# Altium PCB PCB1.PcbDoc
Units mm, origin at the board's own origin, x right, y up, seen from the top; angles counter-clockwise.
Board outline 37.46 x 26.8 mm, 4 copper layers (L1 (Signal), L2 (GND), L3 (GND), L4 (Signal)), stack 1.57 mm thick; 35 components, 27 nets, 170 pads, 47 vias.
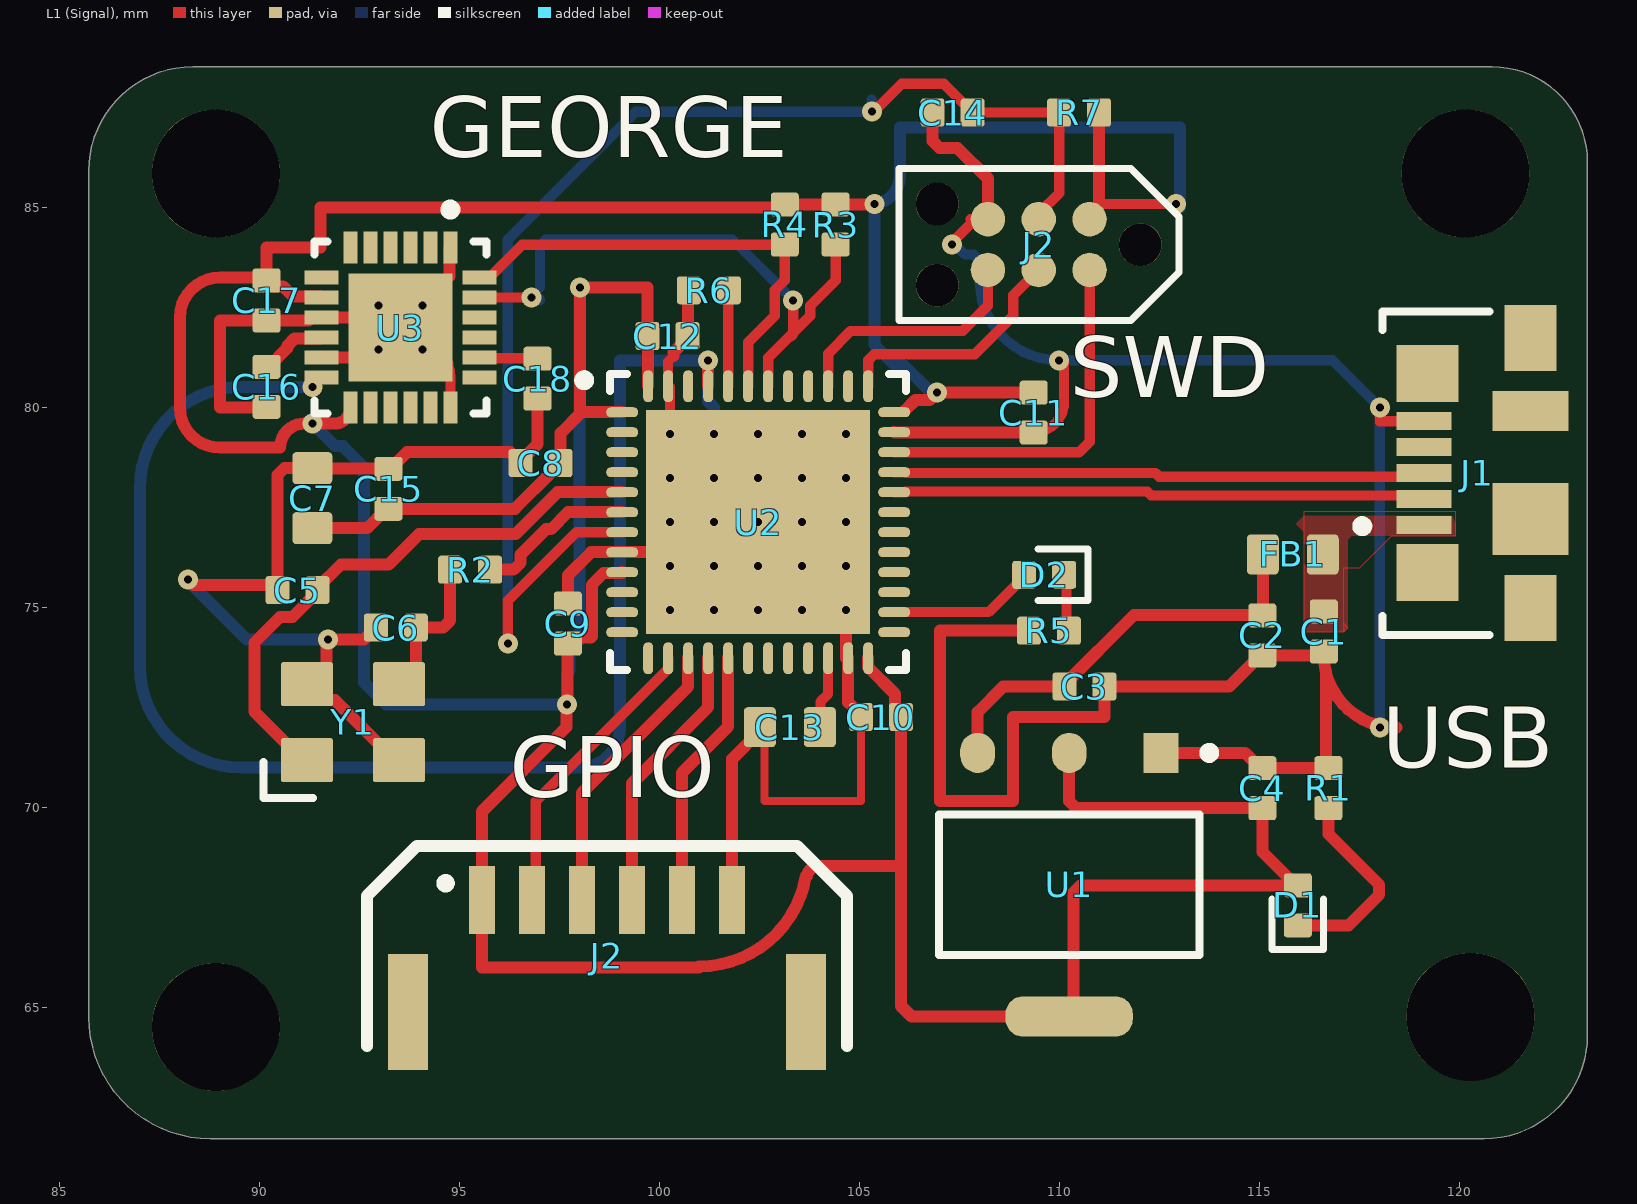
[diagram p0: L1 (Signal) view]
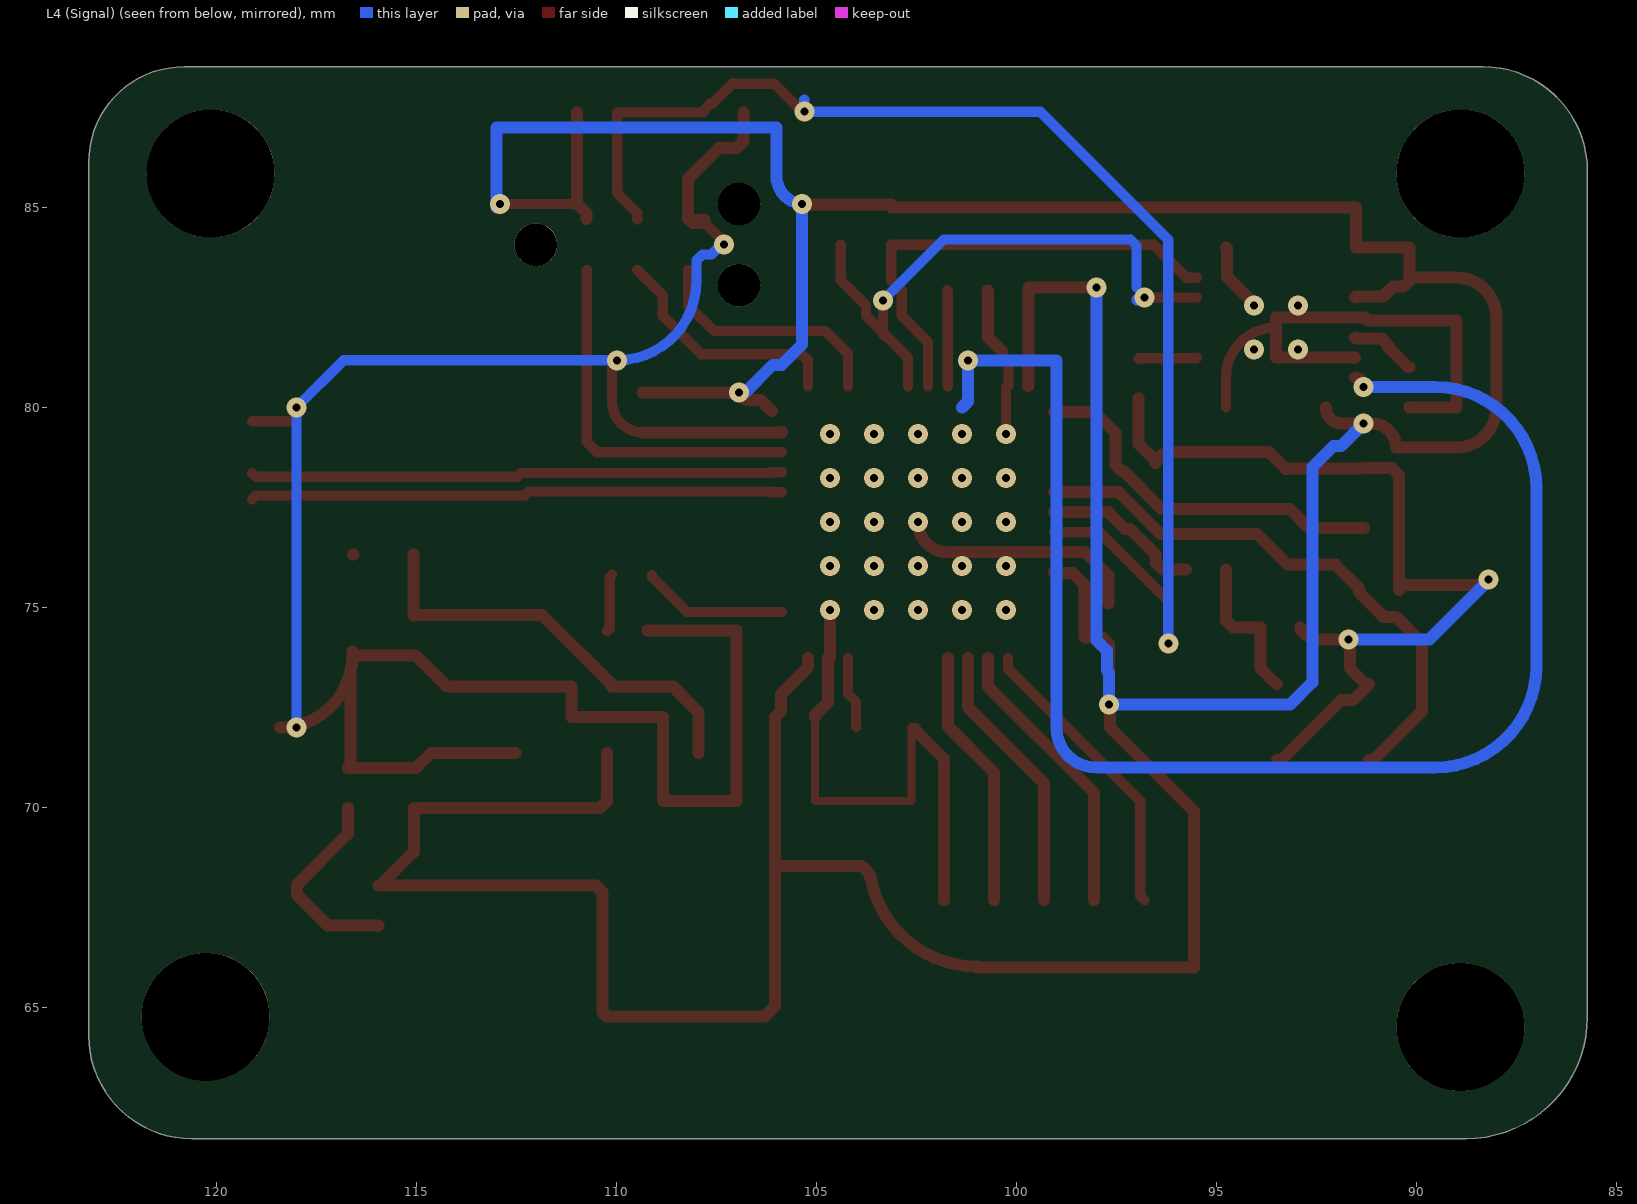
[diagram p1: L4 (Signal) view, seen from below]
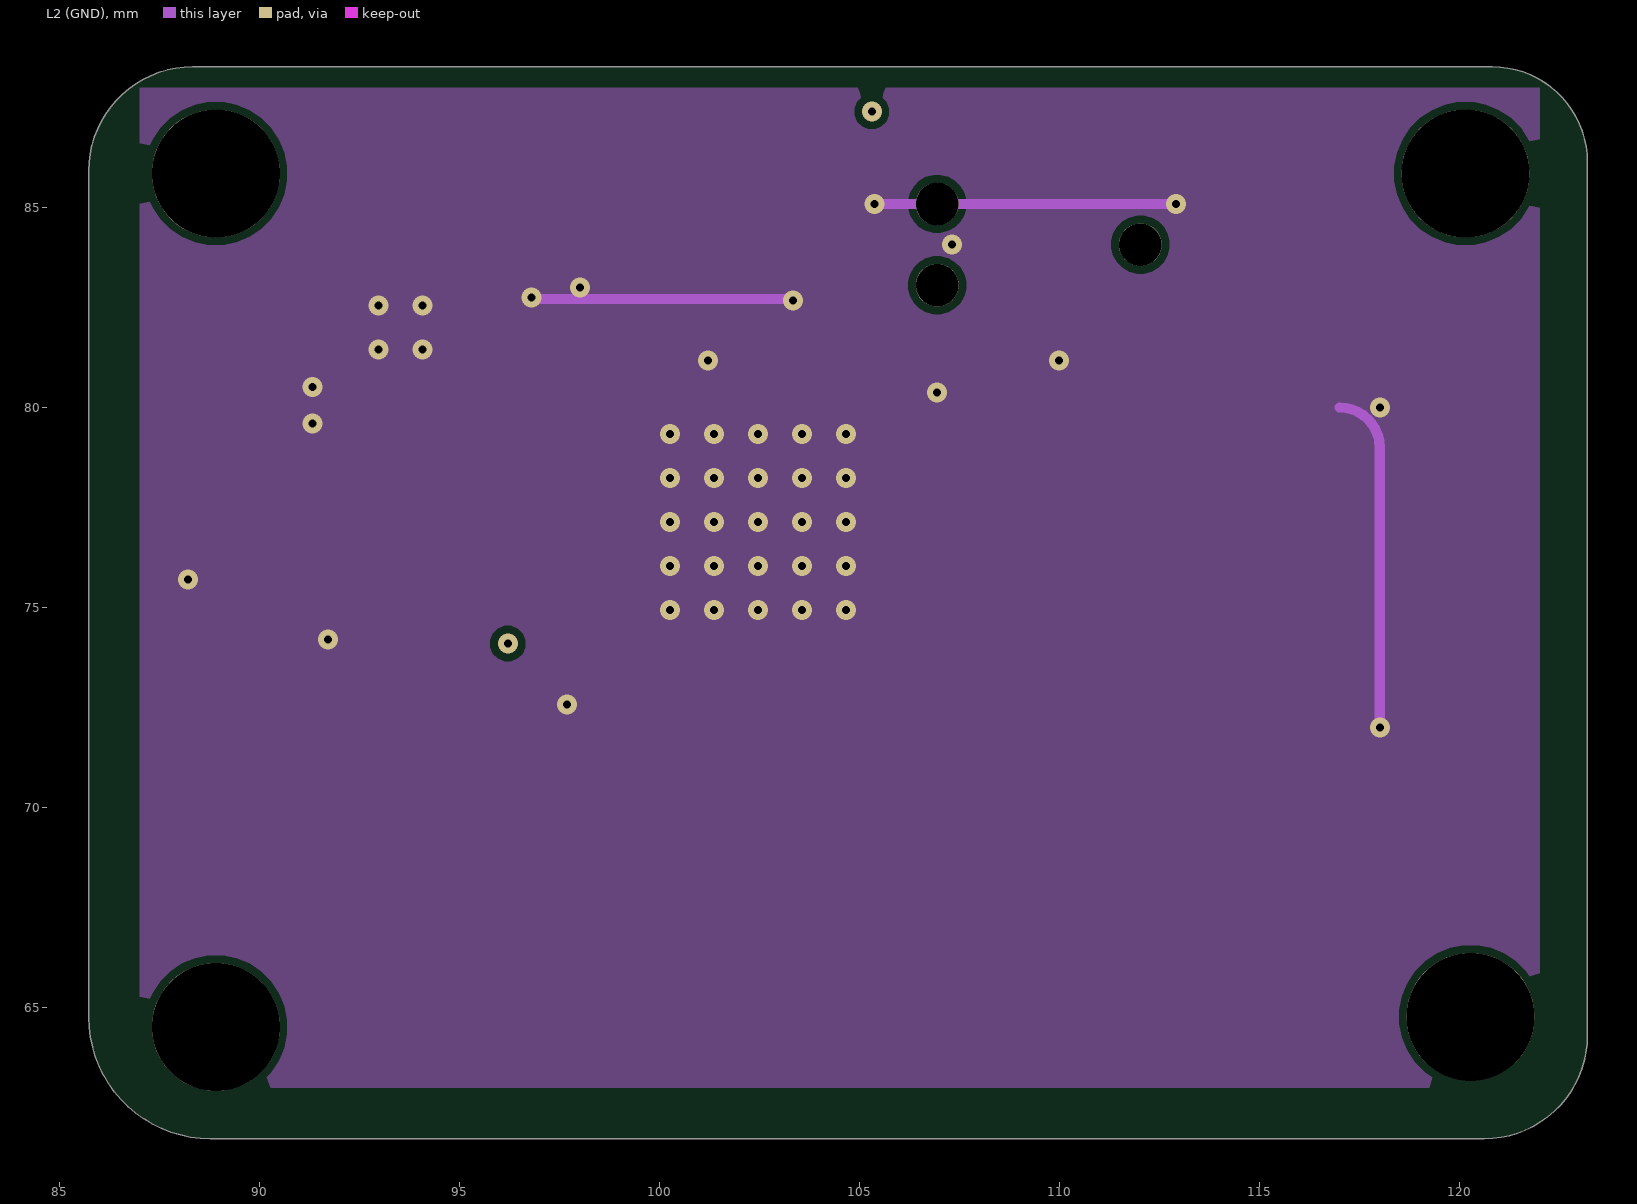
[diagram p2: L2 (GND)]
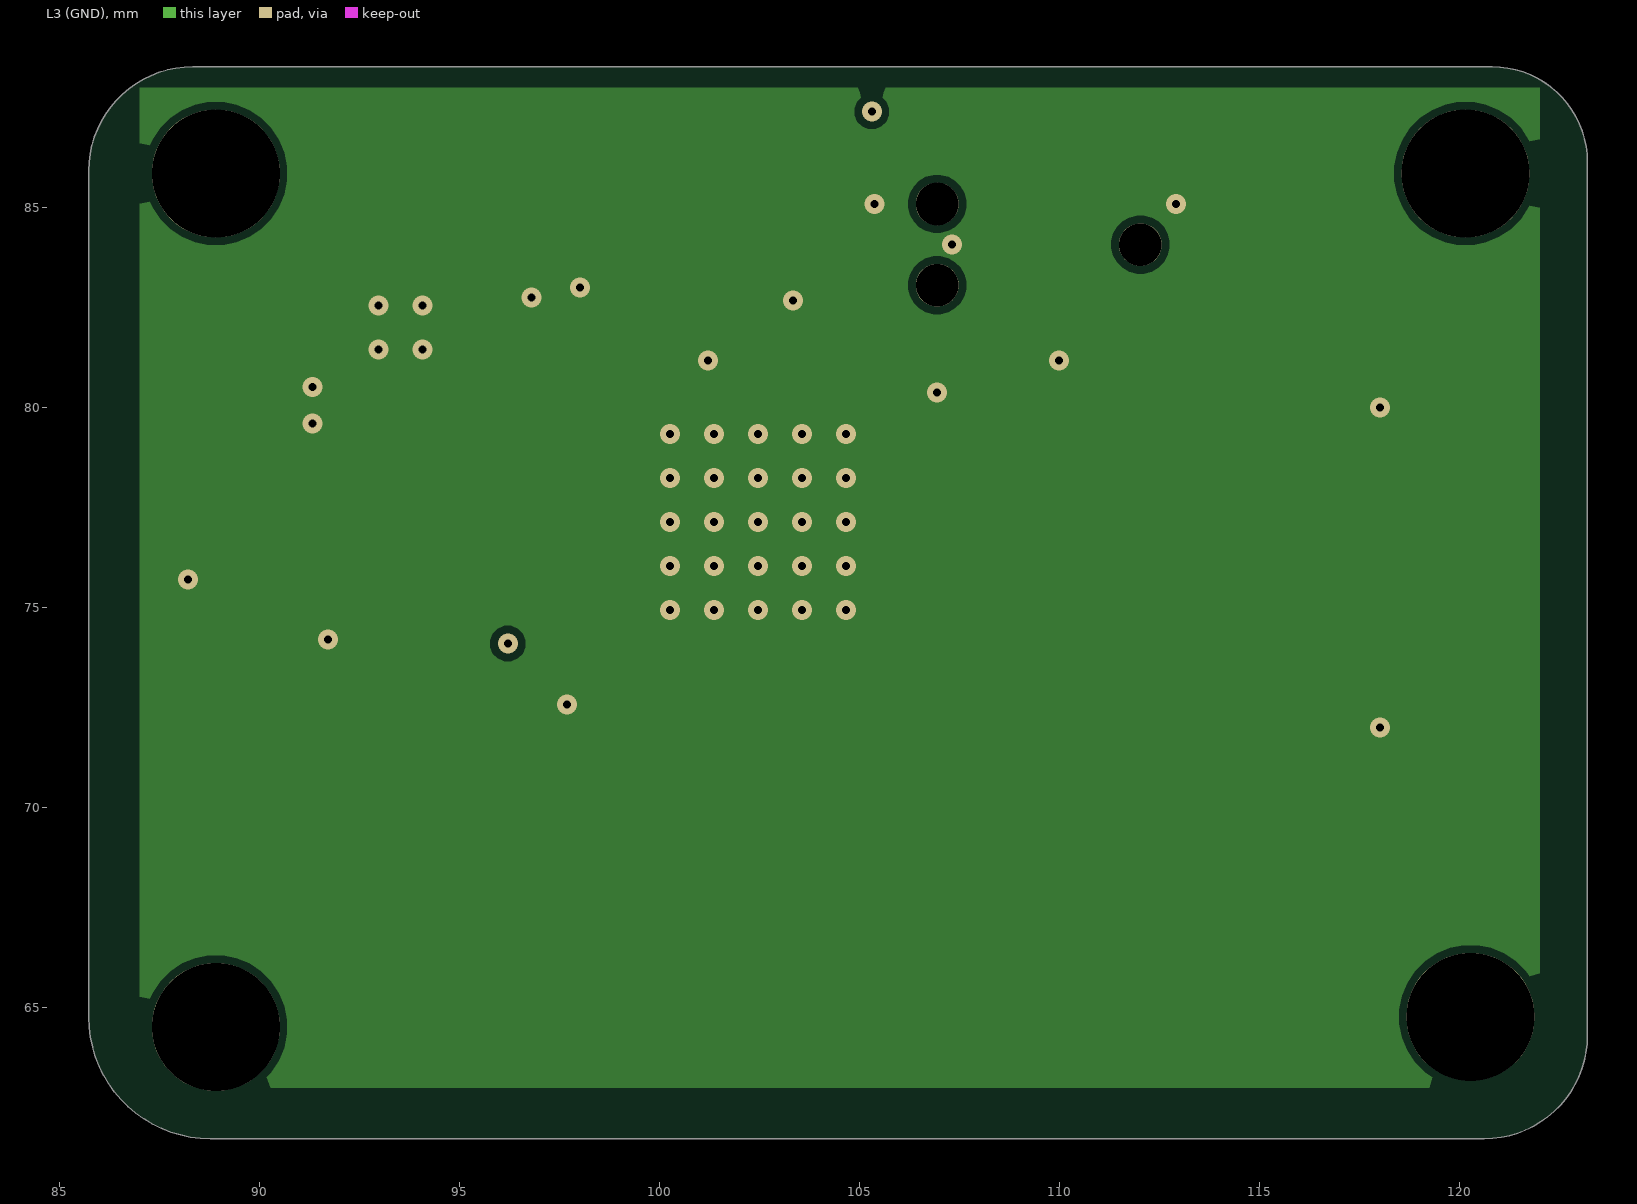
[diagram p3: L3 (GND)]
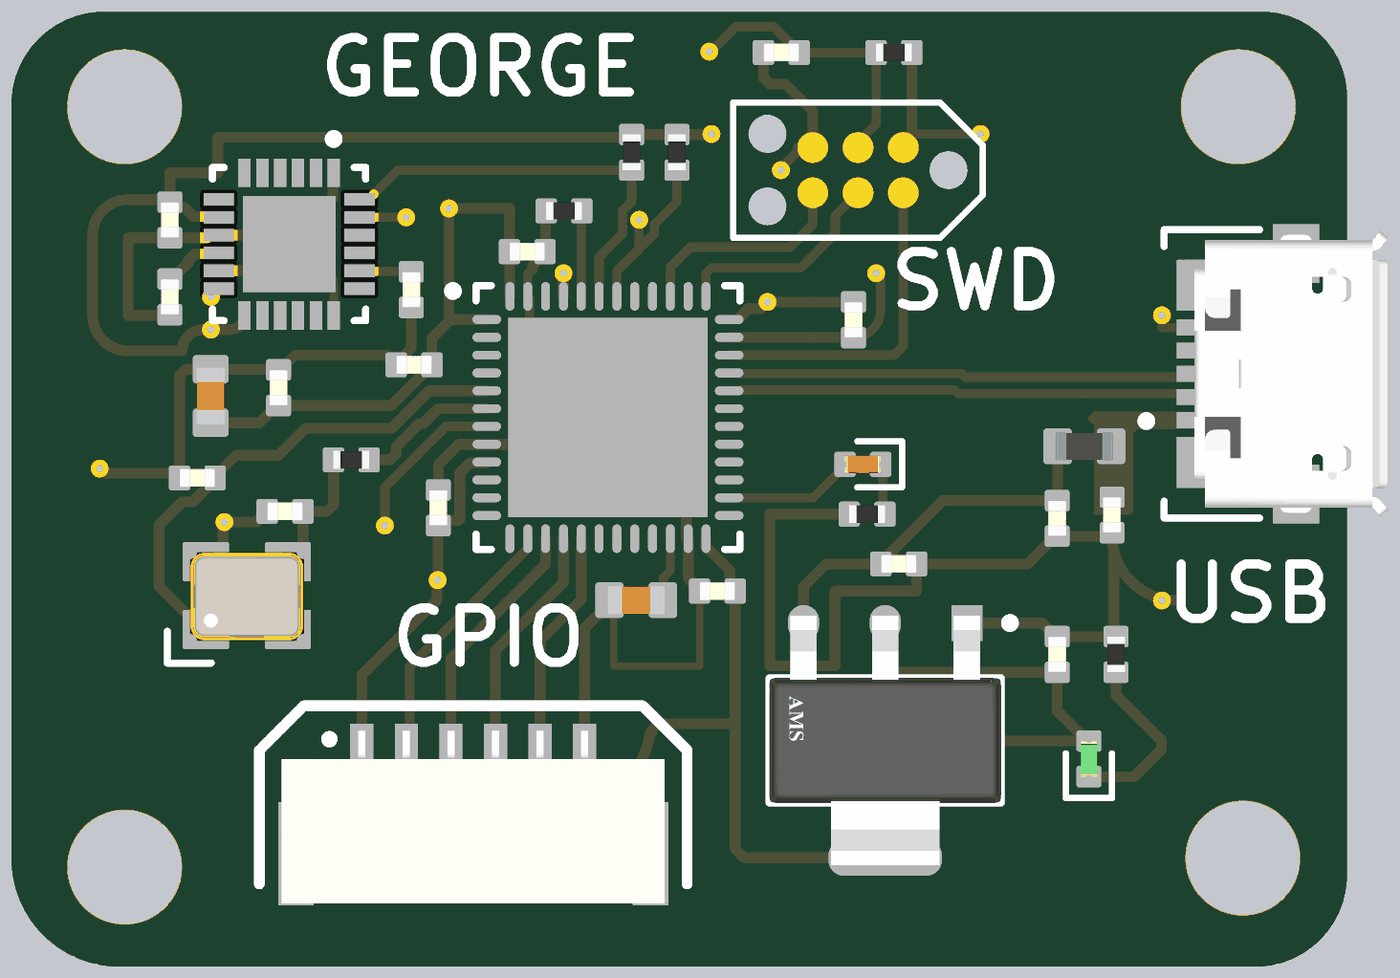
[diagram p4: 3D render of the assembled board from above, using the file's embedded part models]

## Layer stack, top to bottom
Top Solder: solder mask 0.0254, SM-001, Dk 4
L1 (Signal): signal copper 0.035
Dielectric 1: prepreg 0.2, PP-017, Dk 4.6
L2 (GND): signal copper 0.0175
Dielectric 3: core 1.065, Core-039, Dk 4.6
L3 (GND): signal copper 0.0175
Dielectric 5: prepreg 0.2, PP-017, Dk 4.6
L4 (Signal): signal copper 0.035
Bottom Solder: solder mask 0.0254, SM-001, Dk 4

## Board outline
85.725,64.757 85.725,85.917 cw(c88.327,85.917) 88.327,88.519 120.809,88.519 cw(c120.809,86.138) 123.19,86.138 123.19,64.299 cw(c120.613,64.299) 120.613,61.722 88.76,61.722 cw(c88.76,64.757)

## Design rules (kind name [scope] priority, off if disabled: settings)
Clearance [All] p1: gap=0.19 ignorepadtopadclearanceinfootprint=FALSE
DiffPairsRouting [All] p1: maxlimit=0.254 minlimit=0.203 mostfreqgap=0.254 toplayer_maxgap=0.203 toplayer_prefgap=0.203 toplayer_minwidth=0.26 toplayer_maxwidth=0.26 toplayer_prefwidth=0.26 bottomlayer_maxgap=0.203 bottomlayer_prefgap=0.203 bottomlayer_minwidth=0.26 bottomlayer_maxwidth=0.26 bottomlayer_prefwidth=0.26 impedanceprofiledriven=TRUE impedanceprofileid={477ABE33-2594-4362-833C-C7037F59FDB9} impedanceprofilevalue=90.000000 maxuncoupledlength=12.7
PolygonConnect [All] p1: connectstyle=Direct reliefconductorwidth=0.254 reliefentries=4 polygonreliefangle="90 Angle" airgapwidth=0.254
RoutingVias [All] p1: holewidth=0.711 width=1.27 viastyle="Through Hole" minholewidth=0.711 minwidth=1.27 maxholewidth=0.711 maxwidth=1.27
SolderMaskExpansion [All] p1: expansion=0 istentingtop=FALSE
SupplyNets "Schematic Supply Nets_3" [InNet('VBUS')] p1: voltage=0.000
SupplyNets "Schematic Supply Nets_2" [InNet('+3V3')] p2: voltage=0.000
SupplyNets "Schematic Supply Nets_1" [InNet('GND')] p3: voltage=0.000
SupplyNets "Schematic Supply Nets" [InNet('+5V')] p4: voltage=0.000
UnRoutedNet [All] p1: checkbadconnections=TRUE
Width [All] p1: maxlimit=1 minlimit=0.2 preferedwidth=0.3 midlayer1_minwidth=0.254 midlayer1_maxwidth=0.254 midlayer1_prefwidth=0.254 midlayer2_minwidth=0.254 midlayer2_maxwidth=0.254 midlayer2_prefwidth=0.254 minimp=50.000000 maximp=50.000000 favimp=50.000000
28 further rules are at their usual default settings.

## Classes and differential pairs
component class Sheet1: "  R4" "  R5" "  R7" C1 C2 C3 C4 C6 C11 C12 C13 C14 C15 C16 C18 D1 D2 FB1 J1 J2 R1 R2 R6 U1 U2 U3 Y1
differential pair USB_D: +USB_D_P -USB_D_N

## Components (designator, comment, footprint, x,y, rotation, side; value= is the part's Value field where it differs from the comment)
C1 "2u2" CAP_0402 116.6,74.4 r270 top
C2 "2u2" CAP_0402 115.062,74.303 r270 top
C3 "22u" CAP_0402 110.617,73.025 r0 top
C4 "22u" CAP_0402 115.062,70.485 r90 top
C5 "10p" CAP_0402 90.94,75.438 r0 top
C6 "10p" CAP_0402 93.4,74.5 r0 top
C7 "2.2u" CAP_0603 91.313,77.736 r270 top
C8 "100n" CAP_0402 97.02,78.613 r180 top
C9 "100n" CAP_0402 97.7,74.6 r90 top
C10 "100n" CAP_0402 105.529,72.263 r180 top
C11 "100n" CAP_0402 109.347,79.875 r270 top
C12 "100n" CAP_0402 100.195,81.788 r0 top
C13 "2.2u" CAP_0603 103.251,72.009 r0 top
C14 "100n" CAP_0402 107.323,87.376 r180 top
C15 "100n" CAP_0402 93.218,77.97 r90 top
C16 "100n" CAP_0402 90.17,80.518 r270 top
C17 "10n" CAP_0402 90.17,82.677 r270 top
C18 "2n2" CAP_0402 96.943,80.722 r270 top
D1 "GREEN" LED_0402_GREEN 115.951,67.556 r270 top
D2 "RED" LED_0402_RED 109.609,75.819 r0 top
FB1 "120R" FB_0603 115.824,76.327 r180 top
J1 "473460001" FP-473460001-MFG 121.412,78.359 r90 top
J2 "TC2030-NL" TC2030-NL-FP 109.474,84.074 r180 top
J2 "SM06B-GHS-TB" SM06B-GHS-TB 98.679,66.294 r0 top
R1 "1k" RES_0402 116.713,70.485 r270 top
R2 "10k" RES_0402 95.258,75.946 r180 top
R3 "10k" RES_0402 104.394,84.574 r90 top
R4 "10k" RES_0402 103.124,84.574 r90 top
R5 "1k" RES_0402 109.728,74.422 r0 top
R6 "10k" RES_0402 101.227,82.931 r0 top
R7 "10k" RES_0402 110.482,87.376 r0 top
U1 "AMS1117-3.3" FP-ams1117-IPC_C 110.236,68.072 r270 top
U2 "STM32F411CEU6" STM-UFQFPN48_L 102.46,77.133 r0 top
U3 "MPU-6050" IS-QFN-24_V 93.514,82 r270 top
Y1 "24MHz" XTAL_3225 92.329,72.136 r0 top

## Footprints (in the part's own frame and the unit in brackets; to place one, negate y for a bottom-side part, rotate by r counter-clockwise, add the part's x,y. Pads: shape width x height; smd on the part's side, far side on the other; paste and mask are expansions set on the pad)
CAP_0402 [mm]
  rrect25% 0.6x0.7 smd: 1(-0.5,0) 2(0.5,0)
  body extent -0.5,-0.26 0.5,0.26, height 0.37
CAP_0603 [mm]
  rrect25% 0.8x1 smd: 1(-0.75,0) 2(0.75,0)
  body extent -0.8,-0.4 0.8,0.4, height 0.51
FB_0603 [mm]
  rrect25% 0.8x1 smd: 1(-0.75,0) 2(0.75,0)
  body extent -0.8,-0.4 0.8,0.4, height 0.81
FP-473460001-MFG [mm]
  rect 0.45x1.38 smd paste+0 mask+0: 1(-1.3,2.31) 2(-0.65,2.31) 3(0,2.31) 4(0.65,2.31) 5(1.3,2.31)
  rect 1.425x1.55 smd paste+0 mask+0: 6(-2.488,2.225) 7(2.488,2.225)
  rect 1.65x1.3 smd paste+0 mask+0: 8(-3.375,-0.35) 11(3.375,-0.35)
  rect 1.8x1.9 smd paste+0 mask+0: 9(-1.15,-0.35)
  rect 1x1.9 smd paste+0 mask+0: 10(1.55,-0.35)
  silkscreen extent -4.05,0.67 4.05,3.97, body extent -4.3,-2.48 4.3,3.45, height 0.25
FP-ams1117-IPC_C [mm]
  rect 1.004x0.872 smd paste+0 mask+0: 1(-3.295,2.29)
  rrect100% 1.004x0.872 smd paste+0 mask+0: 2(-3.295,0) 3(-3.295,-2.29)
  rrect87% 1.004x3.182 smd paste+0 mask+0: 4(3.295,0)
  silkscreen extent -3.42,-3.25 1.75,3.63, body extent -3.9,-3.35 3.9,3.35, height 0.25
IS-QFN-24_V [mm] "QFN, 24-Leads, Body 4x4mm, Pitch 0.5mm, Thermal Pad 2.7x2.6mm"
  rect 0.8x0.35 smd: 1(-2,1.25) 2(-2,0.75) 3(-2,0.25) 4(-2,-0.25) 5(-2,-0.75) 6(-2,-1.25) 13(2,-1.25) 14(2,-0.75) 15(2,-0.25) 16(2,0.25) 17(2,0.75) 18(2,1.25)
  rect 0.35x0.85 smd mask+0.102: 7(-1.25,-1.975) 8(-0.75,-1.975) 9(-0.25,-1.975) 10(0.25,-1.975) 11(0.75,-1.975) 12(1.25,-1.975) 19(1.25,1.975) 20(0.75,1.975) 21(0.25,1.975) 22(-0.25,1.975) 23(-0.75,1.975) 24(-1.25,1.975)
  rect 2.7x2.6 smd: 25(0,0)
  silkscreen extent -3.07,-2.15 2.15,2.15, body extent -2,-2 2,2, height 0.95
LED_0402_GREEN [mm]
  rrect25% 0.6x0.7 smd: A(-0.5,0) K(0.5,0)
  silkscreen extent -0.15,-0.65 1.1,0.65, body extent -0.51,-0.25 0.51,0.25, height 0.45
LED_0402_RED [mm]
  rrect25% 0.6x0.7 smd: A(-0.5,0) K(0.5,0)
  silkscreen extent -0.15,-0.65 1.1,0.65, body extent -0.51,-0.25 0.51,0.25, height 0.45
RES_0402 [mm]
  rrect25% 0.6x0.7 smd: 1(-0.5,0) 2(0.5,0)
  body extent -0.5,-0.25 0.5,0.25, height 0.3
SM06B-GHS-TB [mm]
  rect 0.65x1.7 smd: 1(-3.125,1.4) 2(-1.875,1.4) 3(-0.625,1.4) 4(0.625,1.4) 5(1.875,1.4) 6(3.125,1.4)
  rect 1x2.9 smd: ""(-4.975,-1.4) ""(4.975,-1.4)
  silkscreen extent -6,-2.25 6,2.75, body extent -5.38,-2.8 5.38,2.05, height 4.26
STM-UFQFPN48_L [mm] "QFN, 48-Leads, Body 7.1x7.1mm, Pitch 0.5mm, Thermal Pad 5.6x5.6mm, IPC High Density"
  oval 0.8x0.25 smd: 1(-3.4,2.75) 2(-3.4,2.25) 3(-3.4,1.75) 4(-3.4,1.25) 5(-3.4,0.75) 6(-3.4,0.25) 7(-3.4,-0.25) 8(-3.4,-0.75) 9(-3.4,-1.25) 10(-3.4,-1.75) 11(-3.4,-2.25) 12(-3.4,-2.75) 25(3.4,-2.75) 26(3.4,-2.25) 27(3.4,-1.75) 28(3.4,-1.25) 29(3.4,-0.75) 30(3.4,-0.25) 31(3.4,0.25) 32(3.4,0.75) 33(3.4,1.25) 34(3.4,1.75) 35(3.4,2.25) 36(3.4,2.75)
  oval 0.25x0.8 smd: 13(-2.75,-3.4) 14(-2.25,-3.4) 15(-1.75,-3.4) 16(-1.25,-3.4) 17(-0.75,-3.4) 18(-0.25,-3.4) 19(0.25,-3.4) 20(0.75,-3.4) 21(1.25,-3.4) 22(1.75,-3.4) 23(2.25,-3.4) 24(2.75,-3.4) 37(2.75,3.4) 38(2.25,3.4) 39(1.75,3.4) 40(1.25,3.4) 41(0.75,3.4) 42(0.25,3.4) 43(-0.25,3.4) 44(-0.75,3.4) 45(-1.25,3.4) 46(-1.75,3.4) 47(-2.25,3.4) 48(-2.75,3.4)
  rect 5.6x5.6 smd: 49(0,0)
  silkscreen extent -4.47,-3.7 3.7,3.7, body extent -3.55,-3.55 3.55,3.55, height 0.6
TC2030-NL-FP [mil]
  round 33.98 smd paste-16.99: 1(-50,-25) 2(-50,25) 3(0,-25) 4(0,25) 5(50,-25) 6(50,25)
  round 42.01 hole 42.01 unplated: MH(-100,0) MH(100,-40) MH(100,40)
  silkscreen extent -138,-75 138,75
XTAL_3225 [mm]
  rrect10% 1.3x1.1 smd: 1(-1.15,-0.95) 2(1.15,-0.95) 3(1.15,0.95) 4(-1.15,0.95)
  silkscreen extent -2.23,-1.89 -1,-1, body extent -1.6,-1.28 1.6,1.22, height 0.61

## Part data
C1 C2 C3 C4 C5 C6 C8 C9 C10 C11 C12 C14 C15 C16 C17 C18: library part CAP_0402, "Capacitor SMD 0402"
C7 C13: library part CAP_0603, "Capacitor SMD 0603"
D1: library part LED_0402_GREEN, "LED 0402 GREEN SMD"
D2: library part LED_0402_RED, "LED 0402 RED SMD"
FB1: library part FB_0603, "Ferrite Bead SMD 0603"
J1: library part CMP-2000-05246-2, "CONN RCPT USB2.0 MICRO B SMD R/A", Current Rating=1.8A, Manufacturer=Molex, Package=0, Temperature="-30°C to +85°C", Temperature Range High=+85°C, Temperature Range Low=-30°C, Voltage Rating=30V
J2: "Tag-Connect No-Solder SWD Debug Connector (No Legs) DO NOT PLACE", Manufacturer=Tag-Connect, Manufacturer Part Number=TC2030-NL-FP
J2: "Header Connector 6 Position 1.25MM Pitch SMD Horizontal JST GH", Manufacturer=JST
R1 R2 R3 R4 R5 R6 R7: library part RES_0402, "Resistor SMD 0402"
U1: library part CMP-209535-000002-1, "1A LOW DROPOUT VOLTAGE REGULATOR"
U2: library part CMP-0243-00165-1, "ARM Cortex-M4 32-bit MCU+FPU, 512 KB Flash, 128 KB RAM, 36 I/Os, 48-Pin UFQFPN, -40 to 85 degC, Tray", I/Os (High Current)=36, Operating Frequency(F) (Processor speed) (MHz)=100, Package Description=UFQFPN48, Package Reference="48-Pin Ultra Thin Fine Pitch Quad Flat No-Lead, 7 x 7 x 0.6 mm Body, 0.5 mm Pitch, Exposed Pad", Supply Voltage(Vcc) min (V)=1.7
U3: library part CMP-1753-00002-2, "3-Axis Gyroscope, Accelerometer and a Digital Motion Processor(TM) (DMP), 2.375 to 3.46 V, -40 to 85 degC, 24-Pin QFN, RoHS, Tape and Reel", Manufacturer=InvenSense, Standard Package=5,000
Y1: library part TSX-3225_24.0000MF15X-AC, "Crystal SMD 24MHz 10PPM 7pF 3225", Manufacturer=Epson, Manufacturer Part Number="TSX-3225 24.0000MF15X-AC"

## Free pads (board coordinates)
  round 3.2 hole 3.2: MH(88.9,64.516) MH(88.9,85.852) MH(120.142,85.852) MH(120.269,64.77)

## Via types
v1: diameter 0.5, hole 0.2, L1 (Signal) to L4 (Signal), 47 vias

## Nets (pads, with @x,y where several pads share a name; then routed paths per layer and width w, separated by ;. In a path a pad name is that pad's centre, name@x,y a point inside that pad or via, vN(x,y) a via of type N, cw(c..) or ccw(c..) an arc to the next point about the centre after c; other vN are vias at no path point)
+3V3: C4.1 C7.2 C8.1 C9.1 C10.1 C11.1 C12.1 C15.1 C17.1 D1.A J2.1 R3.2 R4.2 R7.2 U1.2 U1.4 U2.1 U2.9 U2.24 U2.36 U2.48 U3.8 U3.13 | length 156.3
  L1 (Signal) w0.254: J2.1@110.744,84.709 cw(c111.125,84.709) 111.125,85.09 v1(112.91,85.09)
  L1 (Signal) w0.3: C7.2 92.684,76.986 93.168,77.47 C15.1 96.377,77.47 97.32,78.413 97.37,78.413 97.52,78.563 97.52,79.359 98.044,79.883 ; U3.8 91.514,82.775 90.834,82.775 90.582,83.027 90.32,83.027 C17.1 ; U3.13 cw(c91.864,80) 91.864,79.6 v1(91.321,79.6) 91.11,79.6 ccw(c91.11,79) 90.51,79 89,79 cw(c89,80) 88,80 88,82.25 cw(c89,82.25) 89,83.25 90.097,83.25 cw(c90.097,83.177) C17.1 ; U2.9 99.06,75.858 98.588,75.858 98.3,75.57 98.3,74.276 98.274,74.25 97.85,74.25 97.69,74.09 97.69,72.581 97.662,72.553 97.662,72.008 95.554,69.9 95.554,67.694 95.554,66 100.985,66 ; U2.1 98,79.883 v1(98,83) 99.695,83 C12.1 99.703,81.78 99.703,80.541 U2.48 ; 100.986,66.028 ccw(c100.986,68.728) 103.651,68.294 ; 103.679,68.29 cw(c103.974,68.24) 103.808,68.489 103.883,68.54 105.917,68.54 ccw(c105.917,68.652) 106.029,68.652 ; U2.24 105.21,73.508 105.879,72.839 105.879,72.413 C10.1 106.029,68.652 ; v1(105.362,85.09) 105.362,85.141 cw(c105.296,85.141) 105.296,85.074 R3.2 R4.2 103.124,85 91.514,85 91.514,84 90.17,84 C17.1 ; U2.36@106.11,79.908 106.391,80.189 106.748,80.189 v1(106.934,80.375) C11.1 ; U1.2 110.236,70.161 110.412,69.985 C4.1 115.062,68.895 115.901,68.056 D1.A 110.523,68.056 110.347,67.88 110.347,64.888 U1.4 106.292,64.777 106.029,65.04 106.029,68.54 106.029,68.652 ; J2.1@110.744,84.709 110.744,84.861 110.982,85.099 R7.2
  L2 (GND) w0.254: v1(105.362,85.09) v1(112.91,85.09)
  L4 (Signal) w0.3: v1(91.321,79.6) 91.885,79.036 92.075,79.036 92.602,78.509 92.602,73.129 93.159,72.572 v1(97.681,72.572) 97.681,73.364 97.738,73.422 97.738,73.923 97.998,74.183 97.998,82.998 v1(98,83) ; v1@105.3,85.09 ccw(c105.3,85.79) 106,85.79 106,87 113,87 113,85 ccw(c112.91,85) v1(112.91,85.09) ; v1(105.362,85.09) 105.362,81.572 105.868,81.066 106.091,81.066 106.782,80.375 v1(106.934,80.375)
+5V: C2.1 C3.1 FB1.2 U1.3 | length 10.6
  L1 (Signal) w0.3: U1.3 107.946,72.386 108.585,73.025 C3.1 ; C3.1@110.117,73.075 111.851,74.809 C2.1@115.056,74.809 ; C2.1 115.074,74.815 FB1.2
GND: C1.2 C2.2 C3.2 C4.2 C5.1 C6.1 C7.1 C8.2 C9.2 C10.2 C11.2 C12.2 C13.1 C14.2 C15.2 C16.2 C17.2 C18.2 J1.5 J2.5@108.204,84.709 J2.6@101.804,67.694 R1.1 R5.1 R6.1 U1.1 U2.8 U2.23 U2.35 U2.47 U2.49 U3.1 U3.9 U3.11 U3.18 U3.25 Y1.2 Y1.4 | length 133.7
  L1 (Signal) w0.2: C13.1 102.622,72.009 102.622,70.161 105.029,70.161 C10.2
  L1 (Signal) w0.25: U3.25 cw(c93.514,80.75) 94.764,80.75 U3.18 ; v1(100.26,79.333) 100.26,80.483 ccw(c100.21,80.483) U2.47 100.203,80.54 100.203,81.153 100.345,81.295
  L1 (Signal) w0.254: v1(107.311,84.074) 107.311,84.131 107.772,84.592 108.087,84.592 108.204,84.709 108.087,84.709 J2.5@107.772,84.709 ; C11.2@109.343,79.379 ccw(c109.343,80.145) 110.109,80.145 110.109,81.055 ccw(c109.982,81.055) v1(109.982,81.182) ; v1(118,80) 118,79.659 J1.5
  L1 (Signal) w0.3: v1(88.2,75.7) 88.331,75.569 90.309,75.569 C5.1 90.44,78.31 90.616,78.486 C7.1 91.321,78.478 93.21,78.478 C15.2 ; C16.2 90.17,80 89,80 89,82.177 C17.2 91.216,82.177 91.289,82.25 U3.9 93.514,82.25 U3.25 93.514,81.25 U3.11 ; C6.1 92.9,74.45 92.75,74.3 92.7,74.3 92.6,74.2 v1(91.7,74.2) 91.662,74.162 91.662,73.486 91.262,73.086 Y1.4 91.579,72.686 91.879,72.686 93.379,71.186 Y1.2 ; C15.2@93.268,78.47 93.681,78.883 96.25,78.883 96.32,78.813 96.37,78.813 C8.2@96.52,78.663 ; U3.25@94.064,82.6 94.739,83.275 94.739,83.975 U3.1 ; C8.2 C8.2@96.52,78.663 ; C18.2 96.943,79.086 C8.2@96.52,78.663 ; C9.2 97.7,75.8 98.283,76.383 U2.8 101.71,76.383 ccw(c101.71,77.133) v1(102.46,77.133) ; 100.345,81.295 100.345,81.388 100.711,81.754 100.711,82.915 R6.1 ; J2.6@101.804,67.694 101.804,71.212 C13.1@102.501,71.909 ; v1(104.66,74.933) 104.66,73.733 U2.23 104.71,72.632 105.029,72.313 C10.2 ; U2.35 105.864,79.379 C11.2@109.343,79.379 ; C14.2 106.823,86.663 106.999,86.487 107.442,86.487 108.204,85.725 J2.5@108.204,84.709 ; R5.1 107,74.422 107,70.161 108.831,70.161 108.831,72.263 111.117,72.263 C3.2 114.234,73.025 115.012,73.803 C2.2 C1.2@116.586,73.803 ; U1.1 114.63,71.367 115.012,70.985 C4.2 R1.1 116.649,71.048 116.649,73.391 ; C1.2 116.6,73.812 ccw(c118.412,73.812) 118.412,72 v1(118,72)
  L2 (GND) w0.254: 117,80 cw(c117,79) 118,79 v1(118,72)
  L4 (Signal) w0.254: v1(107.311,84.074) 107.378,84.074 107.628,83.824 107.851,83.824 108,83.675 108,83.164 ccw(c109.982,83.164) v1(109.982,81.182) 116.818,81.182 v1(118,80) v1(118,72)
  L4 (Signal) w0.3: v1(88.2,75.7) 88.2,75.676 89.676,74.2 v1(91.7,74.2)
  other v1: 100.26,74.933 101.36,74.933 102.46,74.933 103.56,74.933 100.26,76.033 101.36,76.033 102.46,76.033 103.56,76.033 104.66,76.033 100.26,77.133 101.36,77.133 103.56,77.133 104.66,77.133 100.26,78.233 101.36,78.233 102.46,78.233 103.56,78.233 104.66,78.233 101.36,79.333 102.46,79.333 103.56,79.333 104.66,79.333 92.964,81.45 94.064,81.45 92.964,82.55 94.064,82.55
IMU_CPOUT: C18.1 U3.20 | length 1.5
  L1 (Signal) w0.26: U3.20 95.503,81.236 96.929,81.236 C18.1
IMU_INT: U2.45 U3.12 | length 37.9
  L1 (Signal) w0.3: v1(91.321,80.519) 91.321,80.532 cw(c91.539,80.532) U3.12 ; U2.45 v1(101.21,81.182)
  L4 (Signal) w0.3: v1(91.321,80.519) 89.54,80.519 ccw(c89.54,77.979) 87,77.979 87,73.54 ccw(c89.54,73.54) 89.54,71 98,71 ccw(c98,72) 99,72 99,81.182 v1(101.21,81.182) 101.21,80.15 101.36,80
IMU_REGOUT: C16.1 U3.10 | length 1.7
  L1 (Signal) w0.3: C16.1 90.22,81.018 90.693,81.491 90.693,81.549 90.869,81.725 91.514,81.725 U3.10
IMU_SCL: R3.1 U2.42 U3.23 | length 21.4
  L1 (Signal) w0.25: U3.23 v1(96.798,82.75)
  L1 (Signal) w0.254: 103.235,81.772 ccw(c103.235,81.872) 103.335,81.872 v1(103.335,82.681)
  L1 (Signal) w0.26: U2.42 102.71,81.247 103.235,81.772 103.759,82.296 103.759,82.55 104.394,83.185 R3.1
  L2 (GND) w0.254: v1(96.798,82.75) 96.833,82.715 103.3,82.715 v1(103.335,82.681)
  L4 (Signal) w0.25: 97,83 97,84.054 97.146,84.2 101.816,84.2 v1(103.335,82.681)
  L4 (Signal) w0.254: v1(96.798,82.75) 96.931,82.75 cw(c96.931,82.681) v1@97,82.681
IMU_SDA: R4.1 U2.43 U3.24 | length 11.9
  L1 (Signal) w0.26: U3.24 95.739,83.25 96.563,84.074 R4.1 103.124,83.185 102.87,82.931 102.87,82.296 102.21,81.636 U2.43
MCU_BOOT0: R6.2 U2.44 | length 2.4
  L1 (Signal) w0.26: U2.44 101.715,80.538 101.715,82.919 R6.2
MCU_LED_A: D2.A U2.26 | length 3.7
  L1 (Signal) w0.25: U2.26 108.223,74.883 109.109,75.769 D2.A
MCU_NRST: C14.1 J2.3@109.474,84.709 R7.1 U2.7 | length 33.6
  L1 (Signal) w0.26: v1(96.2,74.1) 96.2,75.166 97.917,76.883 U2.7 ; v1(105.3,87.4) 105.35,87.4 106.05,88.1 107.099,88.1 107.603,87.596 107.653,87.596 107.823,87.426 C14.1 R7.1 109.982,85.363 109.474,84.855 J2.3@109.474,84.709
  L4 (Signal) w0.26: v1(96.2,74.1) 96.2,84.2 99.4,87.4 v1(105.3,87.4) 105.3,87.7
MCU_OSC_IN: C5.2 U2.5 Y1.1 | length 14.3
  L1 (Signal) w0.3: Y1.1 91.079,71.186 89.865,72.4 89.865,74.124 90.51,74.769 90.821,74.769 91.44,75.388 C5.2 ; C5.2@91.44,75.488 92.025,76.073 93.218,76.073 93.98,76.835 96.393,76.835 97.441,77.883 U2.5
MCU_OSC_OUT: R2.1 U2.6 | length 4
  L1 (Signal) w0.3: R2.1 96.344,75.946 96.52,76.122 96.52,76.327 97.155,76.962 97.282,76.962 97.703,77.383 U2.6
MCU_PA4: J2.2@96.804,67.694 U2.14 | length 7.4
  L1 (Signal) w0.26: J2.2@96.804,67.694 96.901,67.791 96.901,70.159 100.21,73.468 U2.14
MCU_PA5: J2.3@98.054,67.694 U2.15 | length 7.1
  L1 (Signal) w0.3: J2.3@98.054,67.694 98.054,70.368 100.71,73.024 U2.15
MCU_PA6: J2.4@99.304,67.694 U2.16 | length 6.8
  L1 (Signal) w0.3: J2.4@99.304,67.694 99.304,70.602 101.21,72.508 U2.16
MCU_PA7: J2.5@100.554,67.694 U2.17 | length 6.5
  L1 (Signal) w0.3: J2.5@100.554,67.694 100.554,70.87 101.71,72.026 U2.17
MCU_SWCLK: J2.4@109.474,83.439 U2.37 | length 6.1
  L1 (Signal) w0.26: U2.37 105.21,81.182 105.362,81.334 107.877,81.334 108.839,82.296 108.839,82.804 J2.4@109.474,83.439
MCU_SWDIO: J2.2@110.744,83.439 U2.34 | length 9.3
  L1 (Signal) w0.26: U2.34 110.481,78.883 110.744,79.146 J2.2@110.744,83.439
MCU_SWO: J2.6@108.204,83.439 U2.39 | length 6.2
  L1 (Signal) w0.26: U2.39 104.21,81.35 104.775,81.915 107.569,81.915 108.204,82.55 J2.6@108.204,83.439
MCU_VCAP1: C13.2 U2.22 | length 1.8
  L1 (Signal) w0.25: C13.2 104.013,72.021 104.013,72.644 104.21,72.841 U2.22
"Net  R5_2": D2.K R5.2 | length 1.4
  L1 (Signal) w0.26: D2.K 110.168,75.76 110.168,74.482 R5.2
NetD1_K: D1.K R1.2 | length 5
  L1 (Signal) w0.3: D1.K 117.221,67.056 117.986,67.821 117.986,68.069 116.713,69.342 R1.2
USB_D_N: J1.2 U2.32 | length 13.3
  L1 (Signal) w0.26: U2.32 106.125,77.883 106.143,77.901 112.192,77.901 112.291,77.802 119.009,77.802 J1.2
USB_D_P: J1.3 U2.33 | length 13.3
  L1 (Signal) w0.26: U2.33 106.125,78.383 106.143,78.365 112.384,78.365 112.483,78.266 119.009,78.266 J1.3
VBUS: C1.1 FB1.1 J1.1 | length 0
  L1 (Signal) w0.3: FB1.1 FB1.1@116.58,76.321
XTAL_IN: C6.2 R2.2 Y1.3 | length 3.8
  L1 (Signal) w0.3: Y1.3 93.5,73.086 93.9,73.486 C6.2 94.582,74.5 94.758,74.676 R2.2
pads on no net: J1.4 J1.6 J1.7 J1.8 J1.9 J1.10 J1.11 J2. J2.MH U2.2 U2.3 U2.4 U2.10 U2.11 U2.12 U2.13 U2.18 U2.19 U2.20 U2.21 U2.25 U2.27 U2.28 U2.29 U2.30 U2.31 U2.38 U2.40 U2.41 U2.46 U3.2 U3.3 U3.4 U3.5 U3.6 U3.7 U3.14 U3.15 U3.16 U3.17 U3.19 U3.21 U3.22

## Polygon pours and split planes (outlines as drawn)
VBUS on L1 (Signal) "VBUS_L01_P004" (solid, pour order 4): 116.1,77.3 115.9,77.1 116.1,76.9 116.1,74.4 117.1,74.4 117.2,74.5 117.2,76.7 117.3,76.8 119.9,76.8 119.9,77.1 120.1,77.3 116.4,77.3
no net on L1 (Signal) "vbus" (solid, shelved, pour order 0): 117.2,74.5 117.1,74.6 117.1,76 117.5,76 118.3,76.8 119.9,76.8 119.9,77.4 116.1,77.4 116.1,74.4 117.1,74.4 117.2,74.5 117.1,74.6 117.1,74.4 117.1,74.6 117.1,74.4
GND on L2 (GND) "GND_L02_P013" (solid, pour order 13): 87,88 122,88 122,63 87,63 87,88
GND on L3 (GND) "GND_L03_P014" (solid, pour order 14): 87,88 122,88 122,63 87,63

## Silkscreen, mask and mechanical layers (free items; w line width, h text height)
Top Overlay:
  text "GEORGE" at 94.254,86.254 h1.52
  text "SWD" at 110.254,80.254 h1.52
  text "USB" at 118.062,71 h1.52
  text "GPIO" at 96.254,70.254 h1.52
Mechanical 1:
  the board outline again, w0.254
